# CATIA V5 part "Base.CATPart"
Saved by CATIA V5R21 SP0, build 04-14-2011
Part number: Chassi
Bounding box of the stored display mesh (mm): x -50 to 50, y -70 to 70, z -1.5 to 34.5
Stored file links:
  D:\CATIA\CADs\CHASSI\Base.CATPart
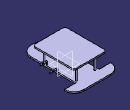
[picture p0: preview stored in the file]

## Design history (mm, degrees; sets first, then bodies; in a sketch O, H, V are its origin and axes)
Body1 (main body)
  Sketch1 on xy-plane, origin (0, 0, 0), H (1, 0, 0), V (0, 1, 0)
    line L1 (-25, 49) -> (-25, -70)
    point P1 (-25, 49)
    point P2 (-25, -70)
    point P3 (-50, 70)
    point P4 (50, 70)
    point P5 (25, 49)
    point P6 (25, -70)
    line L2 (25, 49) -> (25, -70)
    line L3 (-50, 70) -> (50, 70)
    line L4 (-50, 70) -> (-50, 49)
    point P7 (-50, 49)
    line L5 (-50, 49) -> (-25, 49)
    line L6 (-25, -70) -> (25, -70)
    point P8 (50, 49)
    point P9 (50, 70)
    line L7 (50, 70) -> (50, 49)
    point P10 (25, 49)
    line L8 (50, 49) -> (25, 49)
    distance P1 V = 25
    length L1 = 119
    distance P3 V = 50
    distance P3 H = 70
    length L4 = 21
    vertical: L1 V, L4 V
    symmetry: P3 P4 V, P1 P5 V, P2 P6 V, L1 L2 V, P7 P8 V, P3 P9 V, L4 L7 V, P1 P10 V, L5 L8 V
    horizontal: L5 H, L6 H
  Pad1: profile Sketch1, direction (0, 0, 1), length 1.5, mirrored extent
  Sketch2 on end face of Pad1, origin (0, 0, 1.5), H (1, 0, 0), V (0, 1, 0)
    circle A1 centre (-20, 45) radius 2
    point P1 (-20, 45)
    circle A2 centre (-20, -25) radius 2
    point P2 (-20, -25)
    circle A3 centre (20, 45) radius 2
    circle A4 centre (20, -25) radius 2
    distance P1 V = 20
    distance P1 H = 45
    radius A1 = 2
    distance P2 V = 20
    distance P2 H = 25
    radius A2 = 2
    symmetry: A1 A3 V, A2 A4 V
  Pad2: profile Sketch2, direction (0, 0, 1), length 30
  Sketch3 on end face of Pad2, origin (0, 0, 31.5), H (1, 0, 0), V (0, 1, 0)
    point P1 (-35, 55)
    line L1 (-35, 55) -> (35, 55)
    line L2 (35, 55) -> (35, -35)
    line L3 (35, -35) -> (-35, -35)
    line L4 (-35, -35) -> (-35, 55)
    distance P1 V = 35
    distance P1 H = 55
    distance L1 L3 = 90
    distance L2 L4 = 70
    horizontal: L1 H, L3 H
    vertical: L2 V, L4 V
  Pad3: profile Sketch3, direction (0, 0, 1), length 3
  Fillet1: radius 5, on edge [face of Pad3 from Sketch3.L1 | face of Pad3 from Sketch3.L2]; edge [face of Pad3 from Sketch3.L4 | face of Pad3 from Sketch3.L1]; edge [face of Pad3 from Sketch3.L3 | face of Pad3 from Sketch3.L4]; edge [face of Pad3 from Sketch3.L2 | face of Pad3 from Sketch3.L3]
  Fillet2: radius 21, on edge [face of Pad1 from Sketch1.L6 | face of Pad1 from Sketch1.L1]; edge [face of Pad1 from Sketch1.L2 | face of Pad1 from Sketch1.L6]; edge [face of Pad1 from Sketch1.L4 | face of Pad1 from Sketch1.L3]; edge [face of Pad1 from Sketch1.L3 | face of Pad1 from Sketch1.L7]
  Sketch4 on face of Pad1 from Sketch1.L2, origin (25, 0, 0), H (0, 1, 0), V (0, 0, 1)
    circle A1 centre (5, 4.1) radius 1.5
    construction line L1 (49, 0) -> (5, 0)
    point P2 (49, 0)
    reference projected line E1 (49, -1.5) -> (49, 1.5) from edge [face of Fillet2 | face of Pad1 from Sketch1.L8]
    axis line L2 (5, 0) -> (5, 4.1)
    distance P2 E1 = 0
    length L1 = 44
    length L2 = 4.1
    coincidence: P2 H
    horizontal: L1 H
    vertical: L2 V
  Pad4: profile Sketch4, direction (1, 0, 0), length 8.2
  Sketch5 on end face of Pad4, origin (33.2, 0, 0), H (0, 1, 0), V (0, 0, 1)
    arc A1 centre (5, 4.1) radius 1.5 from (6.5, 4.1) to (3.5, 4.1) ccw
    reference projected circle E1 centre (5, 4.1) radius 1.5 from edge [face of Pad4 from Sketch4.A1 | end face of Pad4]
    line L1 (3.5, 4.1) -> (3.5, 7.1)
    line L2 (6.5, 4.1) -> (6.5, 7.1)
    arc A2 centre (5, 7.1) radius 1.5 from (6.5, 7.1) to (3.5, 7.1) ccw
    length L1 = 3
    length L2 = 3
    coincidence: A1 E1
    tangency: L1 A1, A2 L1
  Pad5: profile Sketch5, direction (-1, 0, 0), length 3
  Sketch6 on face of Pad5, origin (33.2, 0, 0), H (0, 1, 0), V (0, 0, 1)
    construction line L1 (49, 0) -> (5, 0)
    point P1 (49, 0)
    reference projected line E1 (49, -1.5) -> (49, 1.5) from edge [face of Fillet2 | face of Pad1 from Sketch1.L8]
    axis line L2 (5, 0) -> (5, 4.1)
    circle A1 centre (5, 4.1) radius 1.5
    distance P1 E1 = 0
    length L1 = 44
    length L2 = 4.1
    radius A1 = 1.5
    coincidence: P1 H
    horizontal: L1 H
    vertical: L2 V
  Pad6: profile Sketch6, direction (1, 0, 0), length 4
  Sketch7 on end face of Pad1, origin (0, 0, 1.5), H (1, 0, 0), V (0, 1, 0)
    axis line L1 (25, 49) -> (25, 5)
    point P1 (25, 49)
    point P2 (25, 5)
    reference projected point E1 (25, 49) from vertex [face of Pad1 from Sketch1.L8 | end face of Pad1 | face of Pad1 from Sketch1.L2]
    line L2 (25, 6.5) -> (22, 6.5)
    line L3 (22, 6.5) -> (22, 3.5)
    line L4 (22, 3.5) -> (25, 3.5)
    line L5 (25, 3.5) -> (25, 6.5)
    distance P1 E1 = 0
    length L1 = 44
    length L4 = 3
    length L3 = 3
    length L2 = 3 (reference)
    vertical: L1 V, L3 V, L5 V
    horizontal: L2 H, L4 H
    coincidence: L5 P2
  Pad7: profile Sketch7, direction (0, 0, 1), length 4.1
  Mirror1: of Pad4, Sketch4, Pad5, Sketch5, Pad6, Sketch6, Pad7, Sketch7, about yz-plane
  Sketch8 on face of Pad7, origin (25, 0, 0), H (0, 1, 0), V (0, 0, 1)
    construction line L1 (49, 0) -> (-17.2, 0)
    point P1 (49, 0)
    reference projected line E1 (49, -1.5) -> (49, 1.5) from edge [face of Fillet2 | face of Pad1 from Sketch1.L8]
    axis line L2 (-17.2, 0) -> (-17.2, 6.5)
    circle A1 centre (-17.2, 6.5) radius 1.5
    distance P1 E1 = 0
    length L1 = 66.2
    length L2 = 6.5
    radius A1 = 1.5
    coincidence: P1 H
    horizontal: L1 H
    vertical: L2 V
  Pad8: profile Sketch8, direction (1, 0, 0), length 8.2
  Sketch9 on end face of Pad8, origin (33.2, 0, 0), H (0, 1, 0), V (0, 0, 1)
    arc A1 centre (-17.2, 6.5) radius 1.5 from (-15.7, 6.5) to (-18.7, 6.5) ccw
    line L1 (-18.7, 6.5) -> (-18.7, 9.5)
    line L2 (-15.7, 6.5) -> (-15.7, 9.5)
    arc A2 centre (-17.2, 9.5) radius 1.5 from (-15.7, 9.5) to (-18.7, 9.5) ccw
    radius A1 = 1.5
    length L1 = 3
    tangency: L1 A1, L2 A1, A2 L1
  Pad9: profile Sketch9, direction (-1, 0, 0), length 3
  Sketch10 on face of Pad9, origin (33.2, 0, 0), H (0, 1, 0), V (0, 0, 1)
    circle A1 centre (-17.2, 6.5) radius 1.5
    reference projected circle E1 centre (-17.2, 6.5) radius 1.5 from edge [face of Pad8 from Sketch8.A1 | face of Pad9]
    radius A1 = 1.5
    concentricity: A1 E1
  Pad10: profile Sketch10, direction (1, 0, 0), length 3
  Sketch11 on end face of Pad1, origin (0, 0, 1.5), H (1, 0, 0), V (0, 1, 0)
    axis line L1 (25, 49) -> (25, -15.7)
    point P1 (25, 49)
    reference projected point E1 (25, 49) from vertex [face of Pad1 from Sketch1.L8 | end face of Pad1 | face of Pad1 from Sketch1.L2]
    line L2 (25, -15.7) -> (25, -18.7)
    line L3 (25, -18.7) -> (22, -18.7)
    line L4 (22, -18.7) -> (22, -15.7)
    line L5 (22, -15.7) -> (25, -15.7)
    length L1 = 64.7
    length L2 = 3
    length L3 = 3
    vertical: L1 V, L2 V, L4 V
    coincidence: P1 E1
    horizontal: L3 H, L5 H
  Pad11: profile Sketch11, direction (0, 0, 1), length 6.5
  Mirror2: of Pad8, Sketch8, Pad9, Sketch9, Pad10, Sketch10, Pad11, Sketch11, about yz-plane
